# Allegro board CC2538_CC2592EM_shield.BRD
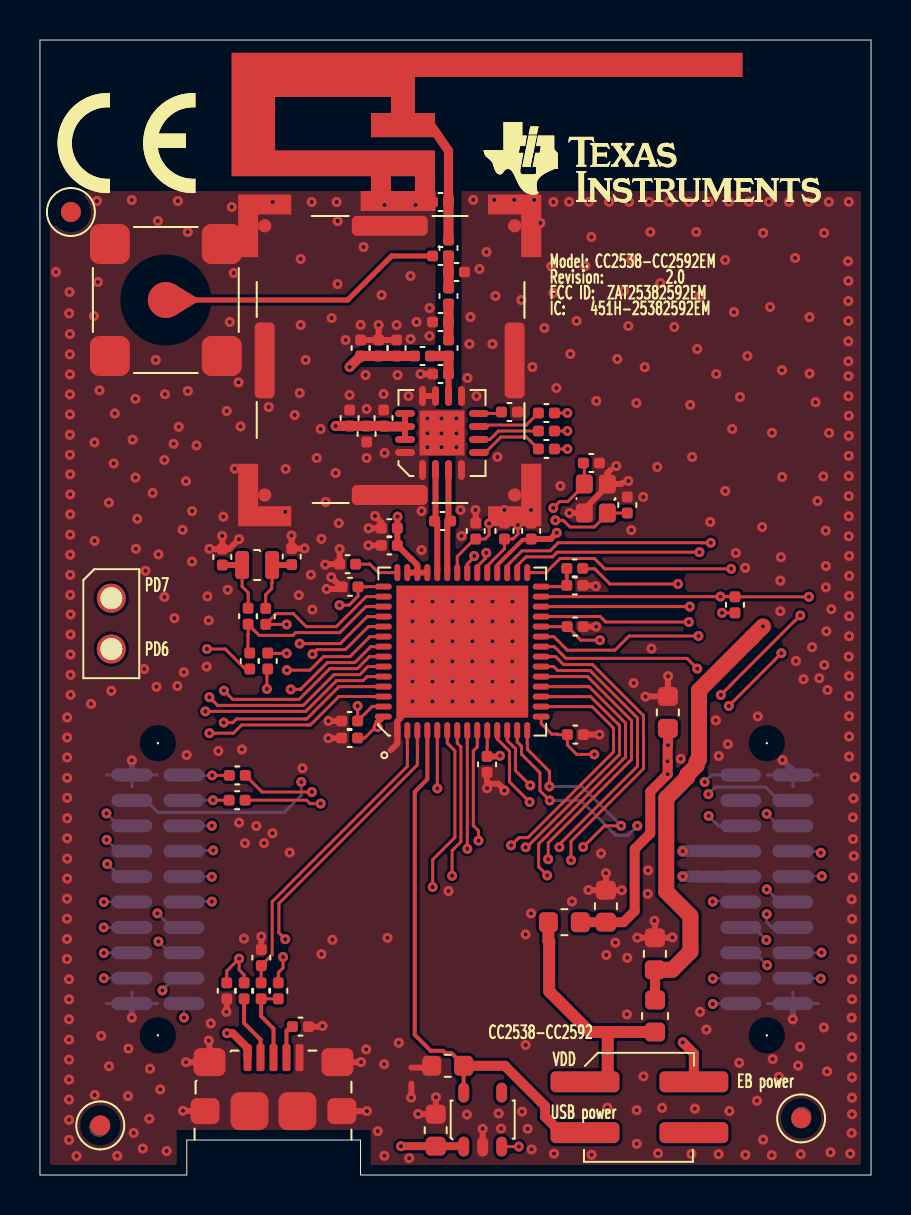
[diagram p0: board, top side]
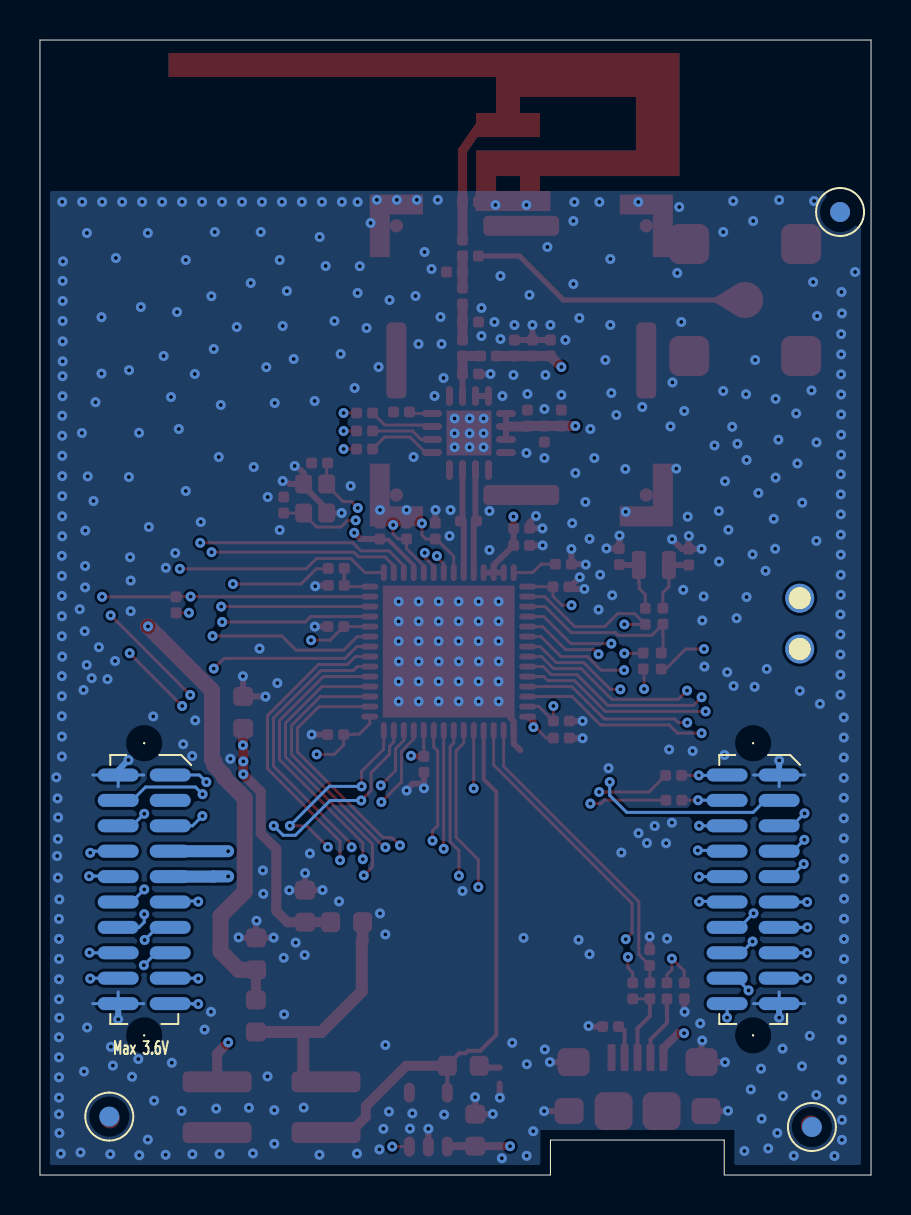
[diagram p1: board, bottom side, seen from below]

Outline 41.6 x 56.75 mm; copper layers: TOP, L2, L3, BOTTOM. Coordinates in mm from the lower left corner of the outline.
Outline path: 0,56.75 0,0 7.35,0 7.35,1.75 16.05,1.75 16.05,0 41.6,0 41.6,56.75 0,56.75

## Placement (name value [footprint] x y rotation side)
A1  DN007  [ANTENNA_DN007]  20.45 48.95 0 top
C2  2.2uF  [CAPC1608X90N]  28.33 12.64 90 top
C3  1uF  [CAPC1608X90N]  19.81 1.44 90 top
C4  DNM  [CAPC1608X90N]  31.43 22.33 90 top
C5  2.2uF  [CAPC1608X90N]  30.78 10.26 90 top
C21  47pF  [CAPC1005X60L]  9.35 9.61 270 top
C31  47pF  [CAPC1005X60L]  11.08 10.47 90 top
C41  1uF  [CAPC1608X90N]  21.21 5.46 180 top
C101  100nF  [CAPC1005X60L]  22.38 20.93 270 top
C151  100nF  [CAPC1005X60L]  26.4 22.02 0 top
C241  100nF  [CAPC1005X60L]  26.39 27.42 0 top
C281  1nF  [CAPC1005X60L]  26.37 29.48 0 top
C321  1uF  [CAPC1005X60L]  24.59 31.8 90 top
C331  100nF  [CAPC1005X60L]  23.25 31.8 90 top
C341  12pF  [CAPC1005X60L]  29.4 33.1 90 top
C351  12pF  [CAPC1005X60L]  27.2 35.6 0 top
C361  100nF  [CAPC1005X60L]  21.81 31.8 90 top
C391  100nF  [CAPC1005X60L]  17.89 32.34 180 top
C392  220pF  [CAPC1005X60L]  17.89 31.48 180 top
C431  100nF  [CAPC1005X60L]  15.92 29.41 180 top
C441  22pF  [CAPC1005X60L]  12.6 30.52 90 top
C451  22pF  [CAPC1005X60L]  9.13 30.5 90 top
C551  1uF  [CAPC1005X60L]  15.9 22.7 180 top
C561  1uF  [CAPC1005X60L]  15.9 21.85 180 top
C3101  3pF  [CAPC1005X60L]  20.45 40.05 180 top
C3103  2.2pF  [CAPC1005X60L]  20.45 42.65 180 top
C3105  0.2pF  [CAPC1005X60L]  20.45 45.15 0 top
C3106  6.8pF  [CAPC1005X60L]  17.85 40.95 90 top
C3107  1nF  [CAPC1005X60L]  16.95 40.95 90 top
C3108  1uF  [CAPC1005X60L]  16.05 40.95 90 top
C3109  DNM  [CAPC1005X60L]  20.45 48.65 180 top
C3110  12pF  [CAPC1005X60L]  20.45 45.95 90 top
C3111  DNM  [CAPC1005X60L]  19.65 45.95 0 top
C3131  12pF  [CAPC1005X60L]  17.2 37.45 90 top
C3132  1nF  [CAPC1005X60L]  16.35 37.45 270 top
C3133  DNM  [CAPC1005X60L]  15.5 37.45 90 top
FIDU1  FIDU_1MM  [FID100X115]  1.55 48.15 0 top
FIDU2  FIDU_1MM  [FID100X115]  3.02 2.48 0 top
FIDU3  FIDU_1MM  [FID100X115]  38.1 2.83 0 top
FIDU4  FIDU_1MM  [FID100X115]  2.96 2.4 180 bottom
FIDU5  FIDU_1MM  [FID100X115]  1.55 48.15 180 bottom
FIDU6  FIDU_1MM  [FID100X115]  38.13 2.92 180 bottom
FL1  BLM18HE152SN1  [FIL_BLM18HE152SN1DN]  27.05 12.64 180 top
FL2  BLM18HE152SN1  [FIL_BLM18HE152SN1DN]  30.79 8.75 270 top
J1  1981568-1  [TYCO_19815681N]  10.39 5.87 270 top
J3  SMA-10V21-TGG  [HUSTSAN_SMA10V21TGGAN]  6.3 43.75 0 top
L3101  4.7nH  [INDC1005X60L]  18.75 40.95 0 top
L3102  1nH  [INDC1005X60L]  20.45 40.95 90 top
L3104  1.8nH  [INDC1005X60L]  20.45 43.55 90 top
L3231  10nH  [INDC1005X60L]  20.55 32.7 180 top
NOREF  -  []  40.6 0 90 top
NOREF#2  -  []  0 53.91 0 top
P1  SFM-110-02-S-D-A-K-TR  [SAMTEC_SFM11002AN]  4.6 20 0 bottom
P2  SFM-110-02-S-D-A-K-TR  [SAMTEC_SFM11002AN]  35.08 20 0 bottom
P5  BB02-HP041-KB3-060B00  [GRADCONN_BB02HP041KB3060B00-4N]  27.28 4.66 270 top
P6  826629-2  [TYCO_826629-2B]  3.57 28.84 270 top
R1  DNM  [RESC1005X40L]  13.44 7.42 180 top
R21  33  [RESC1005X40L]  10.22 9.61 270 top
R31  33  [RESC1005X40L]  11.07 9.61 270 top
R32  1.5k  [RESC1005X40L]  11.93 8.81 90 top
R111  DNM  [RESC1005X40L]  10.27 18.74 180 top
R121  DNM  [RESC1005X40L]  10.28 19.98 180 top
R271  DNM  [RESC1005X40L]  34.79 28.11 90 top
R281  2.2k  [RESC1005X40L]  27.17 30.33 180 top
R421  56k  [RESC1005X40L]  15 30.54 0 top
R441  0  [RESC1005X40L]  11.3 27.53 90 top
R442  DNM  [RESC1005X40L]  11.4 25.3 90 top
R451  0  [RESC1005X40L]  10.42 27.54 90 top
R452  DNM  [RESC1005X40L]  10.5 25.3 90 top
R3051  10k  [RESC1005X40L]  25.75 36.3 180 top
R3061  10k  [RESC1005X40L]  25.75 37.2 180 top
R3071  10k  [RESC1005X40L]  25.75 38.1 180 top
R3081  4.7k  [RESC1005X40L]  23.1 38.15 0 top
SC1  BMIS-201  [MECH_BMIS201]  11.25 34 0 top
U1  CC2538F512RKU  [QFNFC50P800X800X100-57AN]  17.89 22.17 0 top
U2  TLV70233  [SOT95P280X145-5N]  21.21 1.42 0 top
U3  CC2592  [QFNFC65P400X400X100-17AN]  19.15 35.25 0 top
UNK#REFDES  -  []  23.2 52.65 0 top
UNK#REFDES#2  -  []  3.5 49.1 0 top
X1  32MHz  [XTAL_FA128N]  28.4 33.1 90 top
X2  32.768kHz  [XTAL_FC12MN]  11.62 30.5 180 top

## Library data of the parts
A1 = ANTENNA_DN007
C2 C3 C5 C41 = CAPACITOR
C4 = CAPACITOR: alternate symbols: (CAPC1608X90L,CAPC1608X90M)
C21 C31 C101 C151 C241 C281 C321 C331 C341 C351 C361 C391 C392 C431 C441 C451 C551 C561 C3101 C3103 C3105-C3109 C3111 C3131-C3133 = CAPACITOR: alternate symbols: (CAPC1005X60L,CAPC1005X60M)
C3110 = CAPACITOR_HOR: alternate symbols: (CAPC1005X60L,CAPC1005X60M)
FIDU1-FIDU6 = FIDMARK
FL1 = FILTER_2PIN
FL2 = FILTER_2PIN: alternate symbols: (FIL_BLM18HE152SN1DL,FIL_BLM18HE152SN1DM)
J1 = CONN_USB_MICRO_5+6_S
J3 = CONN_COAX_1+4: alternate symbols: (HUSTSAN_SMA10V21TGGL,HUSTSAN_SMA10V21TGGM)
L3101 L3104 L3231 = INDUCTOR: alternate symbols: (INDC1005X60L,INDC1005X60M)
L3102 = INDUCTOR_HOR: alternate symbols: (INDC1005X60L,INDC1005X60M)
P1 P2 = CONN_HEADER_2X10_P_S
P5 = CONN_HEADER_2X2_P_S
P6 = CONN_HEADER_2: alternate symbols: (TYCO_826629-2C,TYCO_826629-2A)
R1 R21 R31 R32 R111 R121 R271 R281 R421 R441 R442 R451 R452 R3051 R3061 R3071 R3081 = RESISTOR: alternate symbols: (RESC1005X40L,RESC1005X40M)
SC1 = SHIELD_COVER_BMIS-201: User Part Number: #PN
U1 = IC_RF_CC2538F512_QFN56_1
U2 = IC_PM_TLV700233_SOT23-5: alternate symbols: (SOT95P280X145-5L,SOT95P280X145-5M)
U3 = IC_RF_CC2592_QFN16_2: alternate symbols: (QFNFC65P400X400X100-17AL,QFNFC65P400X400X100-17AM)
X1 = XTAL_4
X2 = XTAL: alternate symbols: (XTAL_FC12ML,XTAL_FC12MM)

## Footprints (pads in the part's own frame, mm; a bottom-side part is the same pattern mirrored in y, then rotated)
ANTENNA_DN007
  rect 0.46x0.5 smd: 1(0,0)
  rect 1x0.5 smd: 2(-1.18,0) 3(-3.38,0)
CAPC1005X60L
  custom 0.135x0.135 smd: 1(0,0) 2(0.8,0)
CAPC1608X90N
  custom 0.237x0.237 smd: 1(0,0) 2(1.6,0)
FID100X115
  oval 1x1 smd: 1(0,0)
FIL_BLM18HE152SN1DN
  custom 0.237x0.237 smd: 1(0,0) 2(1.6,0)
GRADCONN_BB02HP041KB3060B00-4N
  custom 0.263x0.263 smd: 1(0,0) 2(0,5.45) 3(2.54,0) 4(2.54,5.45)
HUSTSAN_SMA10V21TGGAN
  round 1.801 smd: 1(0,0)
  custom 0.5x0.5 smd: 2(-2.8,-2.8) 3(2.8,-2.8) 4(2.8,2.8) 5(-2.8,2.8)
INDC1005X60L
  custom 0.135x0.135 smd: 1(0,0) 2(0.8,0)
MECH_BMIS201
  custom 0.665x0.665 smd: 1(0,0) 3(12.51,0) 5(12.51,13.46) 7(0,13.46)
  custom 0.25x0.25 smd: 2(6.26,0) 4(12.51,6.73) 6(6.26,13.46) 8(0,6.73)
QFNFC50P800X800X100-57AN
  oval 0.3x0.851 smd: 1(0,0.051) 2(0.5,0.051) 3(1.001,0.051) 4(1.501,0.051) 5(1.999,0.051) 6(2.499,0.051) 7(3,0.051) 8(3.5,0.051) 9(4,0.051) 10(4.501,0.051) 11(5.001,0.051) 12(5.499,0.051) 13(6,0.051) 14(6.5,0.051) 29(6.5,7.95) 30(6,7.95) 31(5.499,7.95) 32(5.001,7.95) 33(4.501,7.95) 34(4,7.95) 35(3.5,7.95) 36(3,7.95) 37(2.499,7.95) 38(1.999,7.95) 39(1.501,7.95) 40(1.001,7.95) 41(0.5,7.95) 42(0,7.95)
  oval 0.851x0.3 smd: 15(7.201,0.749) 16(7.201,1.25) 17(7.201,1.75) 18(7.201,2.25) 19(7.201,2.751) 20(7.201,3.251) 21(7.201,3.749) 22(7.201,4.249) 23(7.201,4.75) 24(7.201,5.25) 25(7.201,5.751) 26(7.201,6.251) 27(7.201,6.749) 28(7.201,7.249) 43(-0.701,7.249) 44(-0.701,6.749) 45(-0.701,6.251) 46(-0.701,5.751) 47(-0.701,5.25) 48(-0.701,4.75) 49(-0.701,4.249) 50(-0.701,3.749) 51(-0.701,3.251) 52(-0.701,2.751) 53(-0.701,2.25) 54(-0.701,1.75) 55(-0.701,1.25) 56(-0.701,0.749)
  rect 6.599x6.599 smd: 57(3.251,4)
QFNFC65P400X400X100-17AN
  oval 0.35x1 smd: 1(0,0) 2(0.65,0) 3(1.3,0) 4(1.95,0) 9(1.95,3.7) 10(1.3,3.7) 11(0.65,3.7) 12(0,3.7)
  oval 1x0.35 smd: 5(2.825,0.875) 6(2.825,1.525) 7(2.825,2.175) 8(2.825,2.825) 13(-0.875,2.825) 14(-0.875,2.175) 15(-0.875,1.525) 16(-0.875,0.875)
  rect 2.25x2.25 smd: 17(0.975,1.85)
RESC1005X40L
  custom 0.135x0.135 smd: 1(0,0) 2(0.8,0)
SAMTEC_SFM11002AN
  round 0.099 hole 1.501 unplated: (1.302,-1.588) (1.302,13.018)
  oval 2.05x0.65 smd: 1(0,0) 2(2.604,0) 3(0,1.27) 4(2.604,1.27) 5(0,2.54) 6(2.604,2.54) 7(0,3.81) 8(2.604,3.81) 9(0,5.08) 10(2.604,5.08) 11(0,6.35) 12(2.604,6.35) 13(0,7.62) 14(2.604,7.62) 15(0,8.89) 16(2.604,8.89) 17(0,10.16) 18(2.604,10.16) 19(0,11.43) 20(2.604,11.43)
SOT95P280X145-5N
  oval 0.549x1.001 smd: 1(0,0) 2(0.95,0) 3(1.9,0) 4(1.9,2.7) 5(0,2.7)
TYCO_826629-2B
  round 1.45 hole 1.1: 1(0,0) 2(2.54,0)
TYCO_19815681N
  custom 0.1x0.1 smd: 1(0,0) 2(0,0.65) 3(0,1.3) 4(0,1.95) 5(0,2.6)
  custom 0.35x0.35 smd: 6(0.225,-1.903) 7(0.225,4.497)
  custom 0.325x0.325 smd: 8(2.675,-2.128) 9(2.675,4.722)
  custom 0.475x0.475 smd: 10(2.675,0.097) 11(2.675,2.497)
XTAL_FA128N
  custom 0.212x0.212 smd: 1(0,0) 2(1.45,0) 3(1.45,1.151) 4(0,1.151)
XTAL_FC12MN
  custom 0.175x0.175 smd: 1(0,0) 2(1.5,0)

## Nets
DVDD_USB: C41.1 P5.3 U1.4(DVDD_USB) U2.5(OUT)
GND: A1.2(GND_2) A1.3(GND_3) C2.2 C3.2 C4.2 C5.2 C21.2 C31.2 C41.2 C101.2 C151.2 C241.2 C281.2 C321.2 C331.2 C341.2 C351.2 C361.2 C391.2 C392.2 C431.2 C441.2 C451.2 C551.2 C561.2 C3101.2 C3103.2 C3105.2 C3106.2 C3107.2 C3108.2 C3109.2 C3131.2 C3132.2 C3133.2 J1.5(GND#5) J1.6(GND#6) J1.7(GND#7) J1.8(GND#8) J1.9(GND#9) J1.10(GND#10) J1.11(GND#11) J3.2 J3.3 J3.4 J3.5 P1.1 P1.19 P2.2 P2.20 R1.1 R421.1 R3081.2 SC1.1(GND#1) SC1.2(GND#2) SC1.3(GND#3) SC1.4(GND#4) SC1.5(GND#5) SC1.6(GND#6) SC1.7(GND#7) SC1.8(GND#8) U1.1(DGND_USB) U1.57(AGND) U2.2(GND) U3.1(GND#1) U3.4(GND#4) U3.9(GND#9) U3.11(GND#11) U3.12(GND#12) U3.16(GND#16) U3.17(EGP/GND) X1.2 X1.4
VDD_CC2538: C2.1 C4.1 C101.1 C151.1 C241.1 C331.1 C361.1 C391.1 C392.1 C431.1 C551.1 FL1.1 U1.10(VDD#10) U1.15(VDD#15) U1.24(VDD#24) U1.33(AVDD#33) U1.36(AVDD#36) U1.39(AVDD#39) U1.40(AVDD#40) U1.41(AVDD#41) U1.43(AVDD_GUARD) U1.55(AVDD_DREG/DVDD1)
VDD_CC2592: C5.1 C3106.1 C3107.1 C3108.1 C3131.1 C3132.1 C3133.1 FL2.1 L3101.1 U3.13(VDD_LNA) U3.14(VDD_BIAS) U3.15(VDD_PA)
VDD_EB: P2.7 P2.9 P5.2
JTAG_TCK: P2.1 U1.47(JTAG_TCK)
JTAG_TMS: P2.4 U1.46(JTAG_TMS)
NRESET: P2.15 R281.1
PA0: P1.7 U1.16(PA0)
PA1: P1.9 U1.17(PA1)
PA2: P1.16 U1.18(PA2)
PA3: P1.14 U1.19(PA3)
PA4: P1.18 U1.20(PA4)
PA5: P1.20 U1.21(PA5)
PA6: P2.5 U1.22(PA6)
PA7: P2.6 U1.23(PA7)
PB0: P1.3 U1.5(PB0)
PB1: P1.5 U1.54(PB1)
PB2: P1.11 U1.53(PB2)
PB3: P1.13 U1.52(PB3)
PB4: P1.15 U1.51(PB4)
PB5: P1.17 U1.50(PB5)
PB6/JTAG_TDI: P2.17 U1.49(PB6)
PB7/JTAG_TDO: P2.19 U1.48(PB7)
PC0: P2.11 R32.2 U1.14(PC0)
PC1: P2.13 U1.13(PC1)
PC2: R121.1 R3061.1 U1.12(PC2)
PC3: R111.1 R3051.1 U1.11(PC3)
PC4: P1.6 U1.9(PC4)
PC5: P1.8 U1.8(PC5)
PC6: P1.10 U1.7(PC6)
PC7: P1.12 U1.6(PC7)
PD0: P2.12 U1.25(PD0)
PD1: P2.14 U1.26(PD1)
PD2: R271.2 R3071.1 U1.27(PD2)
PD3: P2.18 U1.29(PD3)
PD4: P2.8 U1.30(PD4)
PD5: P2.10 U1.31(PD5)
PD6: P6.1 R442.1
PD7: P6.2 R452.1
USB_N: C21.1 R21.1 U1.3(USB_N)
USB_P: C31.1 R31.1 U1.2(USB_P)
N05346: R421.2 U1.42(R_BIAS)
N19179: J1.3(D+) R31.2 R32.1
N23099: C341.1 U1.34(XOSC32M_Q1) X1.1
N24069: J1.4(ID) R1.2
N28244: J1.2(D-) R21.2
N31525: C351.1 U1.35(XOSC32M_Q2) X1.3
N50825: C3.1 J1.1(VBUS) U2.1(IN) U2.3(EN)
N61958: P2.16 R271.1
N118182: FL1.2 FL2.2 P5.1
N130966: R3081.1 U3.8(BIAS)
N292030: P1.2 R121.2
N292096: P1.4 R111.2
N302598: A1.1(FEED_1) C3109.1 C3110.2
N313805: L3231.1 U1.37(RF_P) U3.3(RF_P)
N313817: L3231.2 U1.38(RF_N) U3.2(RF_N)
N314459: R3071.2 U3.7(HGM)
N314634: R3061.2 U3.6(LNA_EN)
N315094: R3051.2 U3.5(PA_EN)
N333392: C3101.1 L3101.2 L3102.1 U3.10(ANT)
N333448: C3105.1 C3110.1 C3111.2 L3104.2
N333456: C3103.1 L3102.2 L3104.1
N355972: C3111.1 J3.1
N359155: C441.1 R441.2 X2.1
N359159: C451.1 R451.2 X2.2
N359209: R451.1 R452.2 U1.45(PD7/XOSC32K_Q2)
N359245: R441.1 R442.2 U1.44(PD6/XOSC32K_Q1)
N359999: C281.1 R281.2 U1.28(NRESET)
N362623: C321.1 C561.1 U1.32(DVDD_REG) U1.56(DCOUPL)

Pads without a net: FIDU1 1; FIDU2 1; FIDU3 1; FIDU4 1; FIDU5 1; FIDU6 1; P2 3; P5 4; U2 4

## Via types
v1: diameter 0.5, hole 0.2, TOP to BOTTOM, 581 vias

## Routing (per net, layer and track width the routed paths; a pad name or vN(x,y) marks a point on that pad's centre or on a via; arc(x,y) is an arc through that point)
DVDD_USB: length 27.7
  TOP w0.2: U2.5 C41.1 21.21,5.48 20.61,6.09 20.29,6.09 20.17,6.21 19.56,6.21 18.76,7.01 18.76,19.16 19.39,19.79 U1.4 ; P5.3 27.27,2.11
  TOP w0.5: C41.1 23.27,5.46 25.29,3.44 25.29,2.91 26.08,2.12 P5.3
GND: length 61.1
  TOP w0.15: C561.2 15.09,21.84 ; C551.2 15.1,22.6 ; 19.52,5.37 C41.2
  TOP w0.3: X1.2 29.1,34.55 29.15,34.6 ; X1.2 28.4,34.45 27.25,33.3 X1.4 v1(26.5,33.1) ; X1.2 28.4,35.1 28.55,35.25 ; 18.59,5.37 19.52,5.37 ; C5.2 31.49,11.86 31.51,11.88 v1(31.66,11.88) ; C5.2 30.07,11.86 30.06,11.87 v1(29.9,11.87) ; C5.2 30.79,11.87 30.79,12.61 30.76,12.64 v1(30.76,12.71) ; 15.06,29.41 15.03,29.41 14.92,29.3 v1(14.35,29.3) ; 15.06,29.41 v1(14.58,29.89) ; 15.06,29.41 C431.2 ; v1(9.96,31.79) 9.47,31.3 C451.2 ; C31.2 v1(11.08,11.92) ; C241.2 v1(27.84,27.42) ; v1(14.14,7.45) 14.03,7.45 14,7.42 R1.1 ; v1(16.45,32.33) 16.61,32.33 16.62,32.34 C391.2 17.1,32.34 17.1,32.62 v1(16.77,32.95) ; v1(23.25,19.22) 23.25,19.26 22.95,19.56 22.38,19.56 ; v1(18.93,3.05) 19.04,3.05 19.05,3.04 C3.2 19.81,3.8 19.82,3.81 v1(19.82,3.89) ; 14.89,5.64 v1(16.07,5.64) ; 22.38,19.56 v1(22.38,19.34) ; 22.38,19.56 C101.2 ; C392.2 v1(16.44,31.48) ; v1(29.12,14.24) 29.12,14.24 C2.2 ; v1(12.59,31.97) 12.59,31.73 12.6,31.72 C441.2 13.16,31.32 13.17,31.33 v1(13.25,31.33) ; J1.8 7.39,3.19 7.38,3.21 v1(7.16,3.21) ; v1(30.31,23.92) 30.32,23.93 C4.2 31.43,24.93 v1(31.44,24.94) ; v1(8.48,31.31) 8.59,31.31 8.6,31.3 C451.2 ; v1(27.45,14.25) 27.65,14.25 27.66,14.24 C2.2 ; v1(9.12,31.95) 9.12,31.82 9.13,31.81 C451.2 ; 15.09,21.84 v1(14.44,21.84) ; v1(28,22.02) C151.2 ; C551.2 v1(14.44,22.7) ; C3101.2 v1(19.05,40.05) ; v1(14.28,30.52) 14.3,30.54 R421.1 v1(15,31.3) ; C2.2 v1(28.33,15.09) ; J1.9 v1(16.36,3.19) ; C21.2 9.35,8.19 9.33,8.17 v1(9.33,8.16) ; v1(23.08,2.32) 23.09,2.31 ; 17.56,21.24 17.89,21.57 U1.1 17.89,22.69 18.05,22.85 18.05,23.05 ; C321.2 24.58,32.61 v1(24.58,33.25) ; C3107.2 C3108.2 ; C3107.2 16.95,42.3 ; C3107.2 C3106.2 ; v1(27.82,29.44) 27.8,29.44 27.76,29.48 C281.2 ; v1(18.58,3.87) 18.58,4.06 18.59,4.07 18.59,4.57 ; v1(22.16,2.31) U2.2 ; v1(8.45,6.72) 8.45,6.6 8.49,6.56 8.49,5.64 7.55,5.64 7.55,5.64 v1(7.31,5.64) ; v1(23.25,33.25) C331.2 ; v1(21.8,33.25) 21.8,33.2 21.81,33.19 C361.2 ; U3.11 U3.12
  BOTTOM w0.15: 3.32,8.57 P1.19 ; P1.19 5.88,8.57 ; P1.19 4.6,9.15 ; P2.2 38.96,20 ; P2.2 37.68,19.42 ; P2.2 36.41,20 ; P2.20 38.96,8.57 ; P2.20 36.41,8.57 ; P2.20 37.68,9.15 ; 3.32,20 P1.1 ; P1.1 4.6,19.42 ; P1.1 5.88,20
  BOTTOM w0.3: v1(37.17,20.75) 37.68,20.24 P2.2 ; P1.19 v1(4.6,7.87) ; P2.20 v1(37.68,7.78) ; P1.1 v1(4.6,20.73)
  vias: v1(0.8,45.15) v1(1.37,22.88) v1(1.36,21.88) v1(1.36,20.88) v1(1.36,19.86) v1(1.36,18.86) v1(1.36,17.83) v1(1.36,16.83) v1(1.36,15.82) v1(1.36,14.82) v1(1.35,13.81) v1(1.35,12.81) v1(1.35,11.8) v1(1.35,10.8) v1(1.48,44.15) v1(1.46,43.08) v1(1.5,42.05) v1(1.5,41.03) v1(1.5,40.03) v1(1.5,39.03) v1(1.5,38.03) v1(1.5,37.01) v1(1.5,36.01) v1(1.52,35.03) v1(1.52,34.03) v1(1.52,33.03) v1(1.52,32.02) v1(1.52,31.02) v1(1.52,30) v1(1.52,29) v1(1.53,28.03) v1(1.53,27.02) v1(1.53,26.02) v1(1.53,25.01) v1(1.53,24.01) v1(1.46,9.79) v1(1.45,8.78) v1(1.45,7.78) v1(1.45,6.77) v1(1.45,5.77) v1(1.46,4.77) v1(1.46,3.77) v1(1.46,2.76) v1(1.46,1.76) v1(1.83,0.95) v1(2.56,23.56) v1(2.7,42.95) v1(2.73,36.63) v1(2.74,31.71) v1(2.74,4) v1(2.85,48.7) v1(2.9,44.65) v1(2.98,39.23) v1(3.07,6.96) v1(3.45,33.62) v1(3.46,5.44) v1(3.57,24.21) v1(3.75,38.08) v1(3.69,35.58) v1(3.87,0.96) v1(4.43,6.32) v1(4.41,3.95) v1(4.6,48.75) v1(4.64,36.77) v1(4.69,2.1) v1(4.78,38.81) v1(4.78,34.87) v1(4.8,31.31) v1(4.87,32.81) v1(5.15,1.33) v1(5.22,25.3) v1(5.28,30.21) v1(5.51,5.32) v1(5.48,2.82) v1(5.64,34.1) v1(5.8,40.75) v1(5.83,24.41) v1(5.9,47.7) v1(5.93,31.03) v1(6.02,4.28) v1(6.23,35.75) v1(6.23,28.9) v1(6.26,39.04) v1(6.34,1.2) v1(6.69,36.56) v1(6.73,27.84) v1(6.9,48.7) v1(6.95,37.41) v1(6.88,24.45) v1(7.14,32.26) v1(7.2,25.14) v1(7.31,34.69) v1(7.34,21) v1(7.4,47.15) v1(7.4,39.2) v1(7.62,33.2) v1(7.61,30.67) v1(7.84,36.48) v1(8.34,25.42) v1(8.38,28.93) v1(8.45,27.73) v1(8.55,7.58) v1(8.93,21.2) v1(9.18,32.92) v1(9.35,38.2) v1(9.4,29.26) v1(9.5,42.65) v1(9.6,48.4) v1(9.7,45.1) v1(9.75,35.32) v1(9.94,39.63) v1(10.04,37.43) v1(9.97,17.62) v1(10.11,21.28) v1(10.21,11.82) v1(10.26,16.59) v1(10.83,17.45) v1(11.22,16.6) v1(11.45,38.4) v1(11.65,48.65) v1(11.64,17.09) v1(12.3,35.3) v1(12.28,33.16) v1(12.5,16.12) v1(12.75,38) v1(13,39.1) v1(12.96,28.99) v1(13.05,45.8) v1(13.05,42.5) v1(13.14,20.34) v1(13.3,40.75) v1(13.6,48.65) v1(13.56,30.01) v1(13.64,28.27) v1(13.85,35.85) v1(14.05,37.3) v1(14.09,31.81) v1(14.09,11.04) v1(14.3,33.65) v1(14.6,42.85) v1(14.64,11.76) v1(14.85,48.65) v1(14.8,35.1) v1(14.9,47.7) v1(14.9,44.55) v1(14.96,32.59) v1(15.3,41.75) v1(15.5,39) v1(16.05,42.5) v1(16.2,46.4) v1(16.3,40) v1(16.33,6.28) v1(16.35,38.3) v1(16.35,35.85) v1(16.95,42.5) v1(16.91,2.19) v1(17.1,44) v1(17.2,39.05) v1(17.23,5.54) v1(17.24,0.96) v1(17.25,48.5) v1(17.25,36.1) v1(17.39,11.86) v1(17.85,42.5) v1(17.9,40) v1(17.96,6.61) v1(18.45,38.95) v1(18.48,0.84) v1(18.55,44.95) v1(18.55,41.8) v1(18.64,28.67) v1(18.64,27.68) v1(18.65,26.69) v1(18.64,25.68) v1(18.65,24.67) v1(18.64,23.68) v1(18.8,48.5) v1(18.85,42.65) v1(19.1,33.2) v1(19.1,31.25) v1(19.39,37.83) v1(19.39,37.08) v1(19.4,36.39) v1(19.5,43.35) v1(19.5,41.95) v1(19.64,28.67) v1(19.64,27.68) v1(19.65,26.69) v1(19.64,25.68) v1(19.65,24.67) v1(19.64,23.68) v1(20.09,37.83) v1(20.09,37.08) v1(20.1,36.39) v1(20.45,14.2) v1(20.64,28.67) v1(20.64,27.68) v1(20.65,26.69) v1(20.64,25.68) v1(20.65,24.67) v1(20.64,23.68) v1(20.84,37.83) v1(20.84,37.08) v1(20.85,36.39) v1(21.05,33.25) v1(21.1,31.95) v1(21.4,39.85) v1(21.37,3.02) v1(21.5,41.55) v1(21.55,42.9) v1(21.64,28.67) v1(21.64,27.68) v1(21.65,26.69) v1(21.64,25.68) v1(21.65,24.67) v1(21.64,23.68) v1(21.69,48.76) v1(21.85,38.95) v1(22,45.3) v1(22.35,46.15) v1(22.65,28.67) v1(22.65,27.68) v1(22.65,26.69) v1(22.64,25.68) v1(22.65,24.67) v1(22.64,23.68) v1(22.74,48.76) v1(22.65,41.55) v1(22.8,43.95) v1(22.9,35.9) v1(22.96,3.08) v1(23.65,28.67) v1(23.65,27.68) v1(23.65,26.69) v1(23.64,25.68) v1(23.65,24.67) v1(23.64,23.68) v1(23.74,48.76) v1(24.1,43.75) v1(24.13,3.17) v1(24.31,12.03) v1(24.31,6.5) v1(24.41,2.31) v1(24.58,13.08) v1(24.61,1.28) v1(24.74,48.76) v1(24.65,40.4) v1(25.05,47.6) v1(25.25,42.35) v1(25.59,45.44) v1(25.7,48.65) v1(25.7,44.1) v1(25.73,1.07) v1(25.85,39.35) v1(26.05,34.45) v1(26.49,48.66) v1(26.55,41.05) v1(26.63,13.68) v1(26.86,42.7) v1(27.3,45.45) v1(27.49,48.66) v1(27.6,46.9) v1(27.61,1.01) v1(27.85,38.7) v1(28.09,16.08) v1(28.35,11) v1(28.4,3.37) v1(28.49,48.66) v1(28.85,35.45) v1(28.8,11.62) v1(28.9,40.8) v1(29.24,44.2) v1(29.45,42.45) v1(29.45,34.7) v1(29.4,10.86) v1(29.38,8.03) v1(29.49,48.66) v1(29.6,45.75) v1(29.6,32.25) v1(29.72,24.6) v1(29.85,38.6) v1(29.87,3.24) v1(29.87,1.56) v1(30.2,33.9) v1(30.21,4.93) v1(30.27,40.39) v1(30.44,15.23) v1(30.42,14.06) v1(30.49,48.66) v1(30.55,47.15) v1(30.61,26.32) v1(30.9,35.4) v1(30.94,1.08) v1(31.05,44.6) v1(31.14,3.36) v1(31.49,48.66) v1(31.75,42.4) v1(32.07,20.81) v1(32.49,48.66) v1(32.55,38.5) v1(32.61,1.05) v1(32.65,35.9) v1(32.85,47.15) v1(32.78,3.32) v1(32.9,41.3) v1(33.02,43.94) v1(33.04,8.16) v1(33.36,7.27) v1(33.49,48.66) v1(33.55,32.65) v1(33.85,40.05) v1(33.83,22.73) v1(33.98,20.95) v1(33.97,1.04) v1(34.3,45.75) v1(34.3,34.2) v1(34.43,21.54) v1(34.49,48.66) v1(34.51,3.2) v1(34.74,43.15) v1(34.65,37.3) v1(34.83,31.1) v1(35.04,38.9) v1(35,5.61) v1(35.3,30.36) v1(35.31,1.01) v1(35.41,40.95) v1(35.49,48.66) v1(35.93,22.93) v1(35.89,3.72) v1(36.2,47.1) v1(36.15,32.4) v1(36.2,1.77) v1(36.49,48.66) v1(36.55,43.4) v1(36.64,37.11) v1(36.63,0.99) v1(36.68,5.8) v1(36.99,4.91) v1(37.14,40.24) v1(37.09,30.89) v1(37.06,29.72) v1(37.06,28.19) v1(37.15,34.9) v1(37.49,48.66) v1(37.8,45.85) v1(37.84,25.7) v1(37.95,5.47) v1(38.05,6.41) v1(38.08,1.04) v1(38.22,24.79) v1(38.49,48.66) v1(38.52,42.89) v1(38.52,40.07) v1(38.65,26.39) v1(38.82,38.64) v1(38.92,33.7) v1(39.01,24.84) v1(39.21,34.93) v1(39.24,7.38) v1(39.25,47.1) v1(39.33,32.22) v1(39.34,30.45) v1(39.34,29.38) v1(39.26,25.5) v1(39.36,27.19) v1(39.42,24.25) v1(39.4,5.18) v1(39.49,48.66) v1(39.5,37.1) v1(39.61,28.29) v1(39.57,1.13) v1(40.45,45.68) v1(40.49,48.66) v1(40.46,44.7) v1(40.46,43.7) v1(40.46,42.7) v1(40.46,41.69) v1(40.46,40.69) v1(40.47,39.94) v1(40.47,38.94) v1(40.49,37.96) v1(40.49,36.96) v1(40.49,35.96) v1(40.49,34.94) v1(40.49,33.94) v1(40.49,32.94) v1(40.49,31.94) v1(40.5,30.96) v1(40.5,29.95) v1(40.5,28.95) v1(40.5,27.94) v1(40.5,26.94) v1(40.49,25.92) v1(40.5,24.94) v1(40.5,23.94) v1(40.5,22.94) v1(40.5,21.92) v1(40.5,20.92) v1(40.63,13.78) v1(40.65,12.81) v1(40.65,11.8) v1(40.65,10.8) v1(40.65,9.79) v1(40.65,8.79) v1(40.63,7.86) v1(40.65,6.89) v1(40.65,5.88) v1(40.65,4.88) v1(40.65,3.87) v1(40.65,3.04) v1(40.63,2.1) v1(40.56,1.07) v1(40.72,18.83) v1(40.69,17.88) v1(40.7,16.8) v1(40.74,15.95) v1(40.7,14.87) v1(40.78,19.88)
VDD_CC2538: length 38.1
  TOP w0.15: v1(27.75,21.03) 26.87,21.03 26.4,21.5 C151.1 25.91,22.02 25.89,22.05 25.61,22.05 25.09,22.57 U1.15 ; v1(23.92,32.5) 23.93,32.49 23.93,32.06 23.67,31.8 C331.1 23.25,31.31 22.39,30.45 U1.33 ; v1(22.48,32.58) 22.48,32 22.28,31.8 C361.1 21.8,31.79 21.74,31.79 20.89,30.93 U1.36 ; U1.55 17.18,23.43 16.63,23.43 C551.1 15.89,22.7 15.9,22.71 v1(15.9,23.45) ; C391.1 17.89,32.33 ; U1.24 C241.1 26.39,27.42 27.07,26.74 v1(28.03,26.74) ; C101.1 22.38,21.41 22.39,21.42 U1.10 ; v1(14.99,28.49) 15.47,28.49 15.92,28.94 C431.1 16.4,29.41 16.41,29.42 U1.43 ; 23,20.93 v1(23.03,20.96)
  TOP w0.3: C101.1 23,20.93 ; v1(17.9,32.92) 17.9,32.34 17.89,32.33 C392.1 17.89,31.48 18.55,30.82 18.57,30.82 18.82,30.57 18.82,30.56 18.89,30.48 U1.40 ; U1.40 U1.39 ; U1.40 U1.41
  TOP w0.5: C4.1 31.44,22.32 v1(31.44,21.49) 31.42,21.47 v1(31.42,20.68) v1(31.42,20.04) 30.55,19.17 30.55,17.08 29.77,16.3 29.77,13.2 29.21,12.64 C2.1 FL1.1
  L3 w0.15: 23.02,20.95 v1(23.03,20.96)
VDD_CC2592: length 63.2
  TOP w0.15: 30.79,10.26 C5.1
  TOP w0.3: U3.13 U3.14 U3.15
  TOP w0.5: L3101.1 C3106.1 C3107.1 C3108.1 v1(15.5,40.4) ; 30.79,8.74 FL2.1 30.79,10.26 ; v1(14.8,37.45) C3133.1 C3132.1 C3131.1 17.22,37.42 U3.14
  TOP w0.8: v1(36.19,27.43) 35.64,26.88 35.64,26.88 32.99,24.23 32.99,20.79 32.87,20.67 32.87,20.48 32.4,20.01 32.4,19.89 31.35,18.84 31.35,14.16 32.56,12.95 32.56,11.17 31.65,10.26 30.79,10.26
  L3 w0.5: v1(15.5,40.4) 14.8,39.7 v1(14.8,37.45) 14.8,36.2 15.85,35.15 26.95,35.15 27.9,36.1 31.3,36.1 36.19,31.21
  L3 w0.8: v1(36.19,27.43) 36.19,31.21
VDD_EB: length 17.7
  TOP w0.5: v1(32.18,6.63) 32.73,6.08 P5.2
  L3 w0.5: v1(32.18,6.63) 32.18,11.48 32.31,11.61 32.31,12.15 32.18,12.28 v1(32.18,14.93) v1(32.18,16.19)
  BOTTOM w0.6: P2.9 32.92,14.92 32.91,14.93 v1(32.18,14.93) ; P2.7 v1(32.18,16.19)
JTAG_TCK: length 35.1
  TOP w0.15: v1(13.64,26.04) 13.87,26.27 15.29,26.27 16.44,27.42 U1.47
  L3 w0.15: v1(33.27,19.65) 31.91,18.29 28.75,18.29 28.55,18.09 13.8,18.09 12.56,19.33 12.56,23.08 12.97,23.49 13.03,23.54 13.16,23.67 13.16,23.67 13.64,24.15 v1(13.64,26.04)
  BOTTOM w0.15: v1(33.27,19.65) 33.62,20 P2.1
JTAG_TMS: length 39.4
  TOP w0.15: U1.46 16.38,27.92 15.03,26.57 v1(13,26.57)
  L3 w0.15: v1(13,26.57) 13,26.06 13.09,25.97 13.09,24.03 12.86,23.8 12.81,23.75 12.26,23.2 12.26,19.21 13.68,17.79 28.67,17.79 28.87,17.99 32.41,17.99 v1(33.46,19.04)
  BOTTOM w0.15: P2.4 36.98,18.73 36.31,19.4 33.82,19.4 v1(33.46,19.04)
NRESET: length 28.8
  TOP w0.15: R281.1 27.19,30.31 27.77,30.31 28.53,29.55 v1(31.94,29.55)
  L3 w0.15: v1(31.94,29.55) 31.94,29.1 31.93,29.09 31.93,26.88 32.19,26.63 32.88,25.93 33.41,25.93 33.41,25.93 33.43,25.91 34.36,24.97 35.3,24.04 35.3,13.13 36.15,12.28 36.77,12.28 37.04,12.01 37.04,11.13 v1(36.4,10.49)
  BOTTOM w0.15: P2.15 35.23,10.96 35.93,10.96 v1(36.4,10.49)
PA0: length 35.5
  TOP w0.15: U1.16 27.64,23.42 28.71,22.35 28.71,21.15 24.43,16.87 24,16.87 23.98,16.85 23.93,16.83 v1(23.58,16.48)
  L3 w0.15: v1(23.58,16.48) 22.91,15.81 19.43,15.81 18.5,14.88 9.94,14.88 9.14,15.69 8.47,15.69 7.72,16.43 3.67,16.43 v1(3.34,16.76)
  BOTTOM w0.15: v1(3.34,16.76) 3.76,16.34 4.45,16.34 P1.7
PA1: length 36.6
  TOP w0.15: v1(24.31,16.39) 24.32,16.39 24.37,16.39 29.01,21.03 29.01,22.47 27.56,23.92 U1.17
  L3 w0.15: v1(24.31,16.39) 23.44,15.51 19.55,15.51 18.62,14.58 9.82,14.58 9.01,15.39 8.34,15.39 7.6,16.13 3.95,16.13 v1(3.37,15.55)
  BOTTOM w0.15: v1(3.37,15.55) 4,14.92 P1.9
PA2: length 36.9
  TOP w0.15: v1(25.39,14.98) 24.96,15.41 24.96,16.55 29.31,20.9 29.31,22.6 27.49,24.42 U1.18
  L3 w0.15: v1(25.39,14.98) 23.95,14.98 22.35,13.38 9.76,13.38 8.05,11.67 v1(5.93,11.67)
  BOTTOM w0.15: v1(5.93,11.67) 6.49,11.11 P1.16
PA3: length 36.4
  TOP w0.15: U1.19 27.41,24.92 29.61,22.72 29.61,20.78 25.44,16.61 v1(25.44,15.79)
  L3 w0.15: v1(5.88,13.08) 9.02,13.08 9.62,13.68 22.1,13.68 24.21,15.79 v1(25.44,15.79)
  BOTTOM w0.15: v1(5.88,13.08) 6.4,12.56 6.4,12.53 6.55,12.38 P1.14
PA4: length 39
  TOP w0.15: v1(26,16.39) 26,16.53 29.91,20.44 29.91,22.85 27.54,25.22 25.92,25.22 25.72,25.42 U1.20
  L3 w0.15: v1(6.13,9.23) 9.97,13.07 10.06,13.07 10.07,13.08 22.55,13.08 23.92,14.45 25.55,14.45 26,14.9 v1(26,16.39)
  BOTTOM w0.15: v1(6.13,9.23) 6.74,9.84 P1.18
PA5: length 40.4
  TOP w0.15: v1(26.58,15.74) 26.58,16.69 30.21,20.32 30.21,22.97 27.66,25.52 26.21,25.52 25.81,25.92 U1.21
  L3 w0.15: v1(26.58,15.74) 26.58,14.99 25.74,14.15 24.06,14.15 22.69,12.78 10.19,12.78 8.21,10.8 8.21,8.23 7.85,7.87 v1(7.21,7.87)
  BOTTOM w0.15: v1(7.21,7.87) 7.21,8.08 7.2,8.09 P1.20
PA6: length 19.4
  TOP w0.15: U1.22 25.74,26.42 26.33,25.83 32.39,25.83 v1(32.9,25.32)
  L3 w0.15: v1(32.9,25.32) 33.59,25.32 34.24,24.67 35,23.91 35,19.48 v1(33.47,17.95)
  BOTTOM w0.15: v1(33.47,17.95) 33.96,17.46 P2.5
PA7: length 22.1
  TOP w0.15: v1(32.96,26.95) 29.49,26.95 28.78,26.24 26.4,26.24 25.72,26.92 U1.23
  L3 w0.15: v1(32.96,26.95) 33.28,26.63 33.56,26.63 33.66,26.53 33.88,26.31 34.61,25.57 34.61,25.57 38.22,21.97 38.3,21.89 38.3,19.98 v1(36.38,18.06)
  BOTTOM w0.15: P2.6 37.64,17.5 36.94,17.5 v1(36.38,18.06)
PB0: length 19.6
  TOP w0.15: U1.5 19.89,19.87 19.89,19.87 v1(19.89,19.33)
  L3 w0.15: v1(19.89,19.33) 19.57,19.65 v1(13.08,19.65)
  BOTTOM w0.15: v1(13.08,19.65) 13.08,18.98 12.23,18.13 5.9,18.13 5.3,18.73 P1.3
PB1: length 19.8
  TOP w0.15: v1(8.48,22.09) 9.68,22.09 10.09,22.5 10.11,22.5 13.39,22.5 13.4,22.5 13.48,22.5 13.48,22.51 13.55,22.51 14.96,23.92 16.55,23.92 16.56,23.92 U1.54
  L3 w0.15: v1(8.48,22.09) 7.84,22.09 7.37,22.56 5.05,22.56 3.33,20.84 v1(3.33,18.08)
  BOTTOM w0.15: P1.5 4.42,17.64 3.77,17.64 v1(3.33,18.08)
PB2: length 24.8
  TOP w0.15: U1.53 16.27,24.42 14.97,24.42 13.35,22.8 13.27,22.8 13.27,22.8 9.83,22.8 9.65,22.62 v1(9.2,22.62)
  L3 w0.15: v1(9.2,22.62) 7.91,22.62 7.67,22.86 7.5,22.86 4.74,22.86 2.85,20.97 2.85,14 v1(3.2,13.65)
  BOTTOM w0.15: v1(3.2,13.65) P1.11
PB3: length 26.7
  TOP w0.15: v1(8.28,23.18) 13.3,23.18 14.84,24.72 16.14,24.72 16.17,24.72 16.37,24.92 U1.52
  L3 w0.15: v1(8.28,23.18) 4.5,23.18 2.55,21.23 2.55,13.02 v1(3.19,12.38)
  BOTTOM w0.15: v1(3.19,12.38) P1.13
PB4: length 29
  TOP w0.15: U1.51 16.42,25.42 16.02,25.02 14.72,25.02 13.18,23.48 8.89,23.48 v1(8.48,23.89)
  L3 w0.15: v1(8.48,23.89) 8.08,23.89 7.71,23.52 4.41,23.52 2.25,21.36 2.25,12.05 v1(3.2,11.1)
  BOTTOM w0.15: P1.15 3.37,11.11 3.36,11.1 v1(3.2,11.1)
PB5: length 31.3
  TOP w0.15: v1(9.21,24.22) 9.65,23.78 12.97,23.78 14.51,25.32 15.89,25.32 16.49,25.92 U1.50
  L3 w0.15: v1(3.2,9.84) 1.95,11.09 1.95,11.92 1.95,11.92 1.95,21.48 4.29,23.82 7.59,23.82 8.31,24.54 8.89,24.54 v1(9.21,24.22)
  BOTTOM w0.15: v1(3.2,9.84) P1.17
PB6/JTAG_TDI: length 43.3
  TOP w0.15: v1(12.55,24.28) 13.04,24.28 13.07,24.31 13.07,24.31 14.38,25.62 15.76,25.62 16.56,26.42 U1.49
  L3 w0.15: v1(33.68,9.82) 33.68,13 33.2,13.47 33.2,14.05 34.15,14.99 34.15,16.38 33.66,16.88 33.02,16.88 32.87,17.03 30.62,17.03 30.59,17 30.54,17 30.07,16.53 29.27,16.53 28.31,17.49 13.55,17.49 11.96,19.08 11.96,23.33 12.56,23.92 12.56,24.27 v1(12.55,24.28)
  BOTTOM w0.15: P2.17 33.89,9.84 33.87,9.82 v1(33.68,9.82)
PB7/JTAG_TDO: length 45.5
  TOP w0.15: U1.48 16.52,26.92 15.52,25.92 14.19,25.92 13.51,25.24 v1(12.36,25.24)
  L3 w0.15: v1(12.36,25.24) 12,24.88 12,23.79 11.66,23.45 11.66,18.96 13.43,17.19 28.19,17.19 29.16,16.22 30.19,16.22 30.67,16.7 32.77,16.7 32.9,16.58 33.38,16.58 33.83,16.13 33.83,15.1 32.9,14.17 32.9,13.35 33.17,13.08 33.17,9.06 v1(33.68,8.55)
  BOTTOM w0.15: v1(33.68,8.55) 33.95,8.55 33.97,8.57 P2.19
PC0: length 40.1
  TOP w0.15: R32.2 11.93,10.09 11.95,10.11 11.95,10.14 12.17,10.36 v1(12.17,10.9) ; v1(29.09,17.46) 28.25,17.46 v1(27.19,16.4) ; v1(25.5,19.43) 25.5,20.18 24.4,21.28 24.4,21.36 24.4,21.4 24.4,21.55 24.39,21.55 24.39,21.57 24.39,21.58 U1.14
  L3 w0.15: v1(29.09,17.46) 29.56,16.98 30.1,16.98 30.48,17.37 32.95,17.37 33.15,17.17 33.78,17.17 34.53,16.42 34.53,14.52 v1(33.68,13.67) ; v1(27.19,16.4) 27.19,15.7 27.19,15.7 27.19,15.17 25.87,13.85 24.22,13.85 22.85,12.48 14.31,12.48 12.73,10.9 v1(12.17,10.9)
  BOTTOM w0.15: P2.11 35.03,13.7 33.85,13.7 33.82,13.67 v1(33.68,13.67) ; v1(29.09,17.46) 27.12,19.43 v1(25.5,19.43)
PC1: length 22.2
  TOP w0.15: v1(25.52,18.72) 25.03,19.22 25.03,20.11 24.1,21.04 24.1,21.34 24.1,21.38 24.1,21.42 24.09,21.42 24.09,21.44 23.89,21.65 U1.13
  L3 w0.15: v1(29.9,17.46) 30.11,17.67 33.08,17.67 33.27,17.47 33.91,17.47 35,16.38 35,12.6 35.85,11.75 v1(36.36,11.75)
  BOTTOM w0.15: v1(36.36,11.75) 35.73,12.38 P2.13 35.06,12.4 ; v1(29.9,17.46) 29.42,16.98 28.82,16.98 28.56,17.24 27.07,18.72 v1(25.52,18.72)
PC2: length 55.7
  TOP w0.15: v1(24.54,19.48) 23.8,20.22 23.8,21.31 23.39,21.73 U1.12 ; R121.1 10.28,19.98 11.11,19.15 v1(13.61,19.15) ; v1(38.06,27.98) 37.74,27.66 37.73,27.66 34.67,24.6 34.67,24.59 v1(34.08,24) ; R3061.1 v1(26.4,37.2)
  L3 w0.15: v1(38.06,27.98) 38.06,28.67 38.01,28.71 38.01,29.11 38.06,29.15 38.06,31.79 32.65,37.2 v1(26.4,37.2) ; v1(34.08,24) 32.89,22.81 32.89,20.8 31.66,19.56 26.7,19.56 26.31,19.96 26.03,20.24 24.85,20.24 24.54,19.93 v1(24.54,19.48) 23.81,18.75 23.05,18.75 23.03,18.77 14.81,18.77 14.53,19.05 13.71,19.05 v1(13.61,19.15)
PC3: length 56.2
  TOP w0.15: v1(37.11,26.09) 36.79,25.77 36.79,25.76 v1(34.48,23.45) ; R3051.1 v1(26.4,36.3) ; v1(14.05,18.57) 13.52,18.57 13.35,18.74 R111.1 ; v1(24.51,18.65) 23.5,19.66 23.5,21.19 22.89,21.8 U1.11
  L3 w0.15: v1(26.4,36.3) 26.9,36.8 32.56,36.8 37.56,31.8 37.56,31.09 37.56,31.09 37.56,30.69 37.56,30.69 37.56,26.54 v1(37.11,26.09) ; v1(24.51,18.65) 24.51,18.62 24.46,18.57 ; v1(24.51,18.65) 25.03,19.17 25.03,19.63 25.3,19.91 25.88,19.91 26.53,19.27 31.78,19.27 33.19,20.67 33.19,21.22 34.48,22.51 v1(34.48,23.45) ; v1(24.51,18.65) 24.3,18.65 24.04,18.39 14.76,18.39 14.58,18.57 v1(14.05,18.57)
PC4: length 21.9
  TOP w0.15: v1(21.95,16.72) 21.95,17.21 21.69,17.47 21.69,21.2 21.89,21.4 21.89,22.22 U1.9
  L3 w0.15: v1(8.61,17.46) 10.59,15.48 18.25,15.48 19.18,16.41 19.18,16.41 19.42,16.65 19.62,16.85 21.82,16.85 v1(21.95,16.72)
  BOTTOM w0.15: v1(8.61,17.46) P1.6
PC5: length 21
  TOP w0.15: U1.8 21.39,21.59 21.39,21.59 v1(21.39,16.31)
  L3 w0.15: v1(21.39,16.31) 19.5,16.31 19.3,16.11 18.37,15.18 10.17,15.18 9.12,16.23 v1(8.67,16.23)
  BOTTOM w0.15: P1.8 7.24,16.23 v1(8.67,16.23)
PC6: length 21.5
  TOP w0.15: U1.7 20.89,21.59 21.07,21.41 21.07,16.66 20.63,16.22 v1(20.63,14.96)
  L3 w0.15: v1(20.63,14.96) 19.43,14.96 18.75,14.28 9.24,14.28 v1(8.61,14.91)
  BOTTOM w0.15: v1(8.61,14.91) 8.6,14.92 P1.10
PC7: length 21.2
  TOP w0.15: v1(19.66,14.4) 19.66,15.77 20.77,16.88 20.77,21.21 20.39,21.59 U1.6
  L3 w0.15: v1(8.6,13.67) 9.06,13.67 9.37,13.98 19.24,13.98 v1(19.66,14.4)
  BOTTOM w0.15: P1.12 7.23,13.68 8.39,13.68 8.4,13.67 v1(8.6,13.67)
PD0: length 26.1
  TOP w0.15: v1(32.48,27.65) 28.32,27.65 28.05,27.92 U1.25
  L3 w0.15: v1(36.38,14.28) 35.83,14.83 35.83,18.46 37.92,20.55 37.92,21.84 34.49,25.27 34.49,25.27 33.67,26.09 33.54,26.23 33.53,26.23 33.01,26.23 32.76,26.47 32.48,26.75 32.48,27.19 32.48,27.2 v1(32.48,27.65)
  BOTTOM w0.15: v1(36.38,14.28) 37.01,13.65 P2.12
PD1: length 28.1
  TOP w0.15: v1(32.53,28.42) 32.08,28.42 32.08,28.42 U1.26
  L3 w0.15: v1(36.38,13.04) 36.91,13.57 36.91,14.86 38.44,16.39 38.44,16.39 38.68,16.63 38.68,21.93 38.52,22.09 38.52,22.09 34.74,25.88 34.1,26.52 33.79,26.83 33.78,26.83 32.98,27.63 32.98,27.97 v1(32.53,28.42)
  BOTTOM w0.15: P2.14 36.64,12.38 36.38,12.64 v1(36.38,13.04)
PD2: length 31.6
  TOP w0.15: v1(38.49,28.91) R271.2 34.78,28.92 v1(34.06,28.92) 33.61,28.92 U1.27 ; R3071.1 v1(26.4,38.1)
  L3 w0.15: v1(38.49,28.91) 38.49,31.81 32.75,37.55 26.95,37.55 v1(26.4,38.1)
PD3: length 35.4
  TOP w0.15: v1(34.6,30.31) 28.27,30.31 27.75,30.83 26.03,30.83 25.33,30.12 U1.29
  L3 w0.15: v1(34.6,30.31) 35.36,29.55 35.36,26.96 39.89,22.43 39.89,17.06 40.2,16.75 40.2,15.67 39.97,15.44 39.97,10.7 v1(39.09,9.82)
  BOTTOM w0.15: P2.18 39.02,9.84 39.04,9.82 v1(39.09,9.82)
PD4: length 28.7
  TOP w0.15: U1.30 23.89,30.47 24.33,30.91 25.66,30.91 25.88,31.12 25.88,31.12 25.9,31.14 v1(33.01,31.14)
  L3 w0.15: v1(39.09,16.11) 39.09,16.59 38.99,16.69 38.99,22.05 38.98,22.06 38.98,22.06 38.82,22.22 38.82,22.22 36.5,24.54 36.5,24.54 34.86,26.18 34.22,26.82 33.91,27.13 33.91,27.13 33.28,27.76 33.28,28.11 33.01,28.38 v1(33.01,31.14)
  BOTTOM w0.15: v1(39.09,16.11) 38.93,16.11 38.85,16.19 P2.8
PD5: length 31.8
  TOP w0.15: v1(33.58,31.61) 33.13,31.61 33.12,31.61 25.94,31.61 25.75,31.42 25.75,31.42 25.54,31.21 24.13,31.21 23.39,30.47 U1.31
  L3 w0.15: v1(33.58,31.61) 33.58,27.89 34.35,27.12 34.99,26.48 34.99,26.48 36.8,24.67 39.29,22.18 39.29,16.81 39.56,16.54 39.56,15.88 39.14,15.46 v1(39.14,14.94)
  BOTTOM w0.15: P2.10 37.71,14.95 38.89,14.95 38.9,14.94 v1(39.14,14.94)
PD6: length 10.7
  TOP w0.15: R442.1 11.36,25.26 v1(11.36,24.3)
  L3 w0.15: P6.1 5.63,26.78 8.88,26.78 v1(11.36,24.3)
PD7: length 7.5
  TOP w0.15: R452.1 10.45,25.3 10.41,25.26 10.41,25.17 9.28,26.3 v1(8.36,26.3)
  L3 w0.15: P6.2 v1(8.36,26.3)
USB_N: length 18.9
  TOP w0.15: U1.3 18.89,20.51 11.96,13.58 11.96,12.11 v1(12.28,11.79) ; C21.1 9.35,10.2 v1(9.97,10.82) 9.97,10.26 10.22,10.01 R21.1
  L3 w0.15: v1(12.28,11.79) 11.31,10.82 v1(9.97,10.82)
USB_P: length 15.6
  TOP w0.15: R31.1 11.07,10.46 C31.1 11.08,10.47 11.62,11.02 11.62,13.67 18.39,20.43 18.39,21.59 18.39,21.59 U1.2
N05346: length 2.3
  TOP w0.15: U1.42 16.94,30.12 16.5,30.56 16.48,30.54 R421.2
N19179: length 4.1
  TOP w0.15: R32.1 R31.2 11.07,8.71
  TOP w0.2: 11.07,8.71 11.07,7.94 11.69,7.32 J1.3
N23099: length 9.4
  TOP w0.15: v1(25.8,32.73) 26.19,32.73 26.53,32.4 27.75,32.4 28.4,33.05 X1.1 C341.1 ; v1(22.34,31.11) 22.28,31.05 22.28,30.82 21.89,30.43 21.89,30.12 U1.34
  L3 w0.15: v1(25.8,32.73) 25.48,32.41 25.47,32.41 24.17,31.11 v1(22.34,31.11)
N24069: length 1.7
  TOP w0.15: R1.2 12.54,7.42 ; 12.34,6.25 J1.4
  TOP w0.2: 12.34,6.25 12.34,7.22 12.54,7.42
N28244: length 3.3
  TOP w0.15: R21.2 10.22,8.71
  TOP w0.2: J1.2 11.04,6.77 10.21,7.6 10.21,8.15 10.22,8.16 10.22,8.71
N31525: length 9.2
  TOP w0.15: v1(25.69,33.35) 26.01,33.67 26.42,33.67 27.25,34.5 X1.3 27.25,35.55 C351.1 ; v1(21.73,30.95) 21.73,30.89 21.39,30.55 U1.35
  L3 w0.15: v1(25.69,33.35) 24,31.66 22.21,31.66 21.73,31.18 v1(21.73,30.95)
N50825: length 24.9
  TOP w0.15: U2.3 v1(23.97,1.42)
  TOP w0.4: v1(18.07,1.44) C3.1 21.19,1.44 U2.1 ; J1.1 10.39,6.34 9.64,7.09 v1(9.36,7.09)
  L3 w0.15: v1(23.97,1.42) 18.54,1.42 18.52,1.44 v1(18.07,1.44)
  L3 w0.4: v1(9.36,7.09) 9.36,5.28 10.13,4.51 16.8,4.51 18.07,3.24 v1(18.07,1.44)
N61958: length 21.8
  TOP w0.15: R271.1 v1(34.14,28.11)
  L3 w0.15: v1(39.12,11.12) 39.67,11.67 39.67,15.56 39.86,15.76 39.86,16.66 39.59,16.94 39.59,22.3 37.1,24.79 35.11,26.78 34.46,27.43 34.46,27.79 v1(34.14,28.11)
  BOTTOM w0.15: v1(39.12,11.12) 39.11,11.11 P2.16
N118182: length 13.1
  TOP w0.5: P5.1 28.14,4.66 28.42,4.94
  TOP w0.6: FL2.2 28.42,7.15 ; 28.42,7.15 27.52,7.15 25.49,9.18 25.49,11.67 25.45,11.71 FL1.2 ; 28.42,7.15 28.42,4.94
N130966: length 1.2
  TOP w0.15: R3081.1 23.03,38.07 U3.8
N292030: length 2.3
  TOP w0.15: R121.2 v1(8.62,19.98)
  BOTTOM w0.15: v1(8.62,19.98) 7.22,19.98 P1.2
N292096: length 2.3
  TOP w0.15: R111.2 v1(8.66,18.74)
  BOTTOM w0.15: P1.4 7.21,18.74 v1(8.66,18.74)
N302598: length 2.2
  TOP w0.5: A1.1 C3109.1 C3110.2
N313805: length 5.4
  TOP w0.15: L3231.1 20.44,32.7 20.39,32.75
  TOP w0.3: L3231.1 20.45,32.8 U3.3 ; 20.39,32.75 U1.37
N313817: length 5.3
  TOP w0.15: L3231.2 19.89,32.7
  TOP w0.3: U3.2 19.8,32.75 L3231.2 ; 19.89,32.7 U1.38
N314459: length 3.3
  TOP w0.15: U3.7 22.05,37.5 24.34,37.5 24.94,38.1 R3071.2
N314634: length 3.2
  TOP w0.15: R3061.2 22.95,37.2 22.52,36.78 U3.6
N315094: length 3.5
  TOP w0.15: U3.5 22.3,36.12 23.07,36.9 24.34,36.9 24.94,36.3 R3051.2
N333392: length 2.9
  TOP w0.3: U3.10 C3101.1
  TOP w0.5: C3101.1 L3102.1 L3101.2
N333448: length 1.6
  TOP w0.5: L3104.2 C3105.1 C3110.1
N333456: length 1.8
  TOP w0.5: L3104.1 C3103.1 L3102.2
N355972: length 14.3
  TOP w0.26: J3.1 15.4,43.75 17.6,45.95 C3111.1
N359155: length 3.3
  TOP w0.15: R441.2 11.3,29.02 11.6,29.32 11.6,29.58 11.62,29.6 X2.1
  TOP w0.3: C441.1 12.58,30.5 X2.1
N359159: length 3.3
  TOP w0.15: X2.2 10.12,29.42 10.42,29.12 R451.2
  TOP w0.3: X2.2 C451.1
N359209: length 9.2
  TOP w0.15: R452.2 10.45,26.1 10.41,26.06 10.41,27 10.42,27.01 10.42,27.53 ; 10.42,27.53 R451.1 ; 10.42,27.53 10.97,26.98 12.66,26.98 12.8,27.12 15.01,27.12 16.31,28.42 U1.45
N359245: length 10.5
  TOP w0.15: v1(12.35,26.08) 11.38,26.08 R442.2 ; v1(12.35,27.53) R441.1 11.3,27.53 11.83,28.07 12.68,28.07 13.33,27.42 14.83,27.42 16.33,28.92 U1.44
  L3 w0.15: v1(12.35,27.53) v1(12.35,26.08)
N359999: length 3.1
  TOP w0.15: 26.35,30.31 26.39,30.31 ; 26.35,30.31 R281.2 ; 26.35,30.31 26.35,29.57 26.2,29.42 U1.28 ; 26.39,30.31 26.49,30.31 ; 26.39,30.31 26.39,29.5 C281.1
N362623: length 23.1
  TOP w0.15: 16.89,22.38 16.79,22.38 16.25,21.85 C561.1
  TOP w0.2: C321.1 24.55,31.76 24.16,31.76 22.89,30.49 22.89,30.12 U1.32
  TOP w0.3: U1.56 16.89,22.62 16.89,22.38 v1(16.9,22.39) ; v1(25.87,32.11) 25.56,31.8 C321.1
  L3 w0.3: v1(25.87,32.11) 24.25,30.49 24.25,23.27 24.04,23.06 18.1,23.06 17.43,22.39 v1(16.9,22.39)

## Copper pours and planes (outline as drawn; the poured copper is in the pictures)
GND on TOP (solid shape): 19.8,48.2 16.05,48.2 16.05,49.2 19.8,49.2
GND on TOP: 0.5,0.5 0.5,49.2 19.8,49.2 19.8,41.5 16.05,41.5 16.05,40.4 19.8,40.4 19.8,38.3 21.1,38.3 21.1,49.2 41.1,49.2 41.1,0.5 16.55,0.5 16.55,2.25 6.85,2.25 6.85,0.5 ; 11 cut-outs
GND on BOTTOM: 0.5,0.5 0.5,49.2 41.1,49.2 41.1,0.5 16.55,0.5 16.55,2.25 6.85,2.25 6.85,0.5 ; 1 cut-out
GND on L2: 0.5,0.5 0.5,49.2 41.1,49.2 41.1,0.5 16.55,0.5 16.55,2.25 6.85,2.25 6.85,0.5 ; 1 cut-out
GND on L3: 0.5,0.5 0.5,49.2 41.1,49.2 41.1,0.5 16.55,0.5 16.55,2.25 6.85,2.25 6.85,0.5 ; 15 cut-outs
VDD_CC2538 on L3: 31.6,19.7 17.5,19.7 14.6,22.6 14.6,30.3 19.2,34.9 26.8,34.9 32.9,28.8 32.9,21 ; 1 cut-out
Net_24 on TOP (solid shape): 35.17,54.9 18.77,54.9 18.77,53.1 19.77,53.1 19.77,52.6 20.68,51.28 20.68,49.2 20.22,49.2 20.22,51.13 19.7,51.89 16.57,51.89 16.57,53.1 17.57,53.1 17.57,53.9 11.77,53.9 11.77,51.23 19.77,51.23 19.77,49.2 18.77,49.2 18.77,49.94 17.57,49.94 17.57,49.2 16.57,49.2 16.57,49.94 9.59,49.94 9.59,56.11 35.17,56.11
N362623 on L3: 18.05,23 18.05,29.35 22.9,29.35 24.2,30.65 24.3,30.65 24.3,23

Small or netless copper shapes (teardrops, artwork), in the pictures only: 1 on TOP

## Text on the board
Ref Des/Silkscreen Bottom: Max 3.6V
Ref Des/Silkscreen Top: PD7 | PD6 | CC2538-CC2592 | Model: CC2538-CC2592EM | Revision:          2.0 | FCC ID:  ZAT25382592EM | IC:    451H-25382592EM | USB power | VDD | EB power
XSECTION_CHART: L1: TOP CONDUCTOR - COPPER 0.035 MM | *  DIELECTRIC - FR-4 0.175 MM | L2: L2 PLANE - COPPER 0.018 MM | *  DIELECTRIC - FR-4 1.14 MM | L3: L3 PLANE - COPPER 0.018 MM | L4: BOTTOM CONDUCTOR - COPPER 0.035 MM | DESIGN CROSS SECTION CHART | ___________________________ | TOTAL THICKNESS 1.596 MM
DIMENSION: FIGURE | SIZE | 0.2 | 1.1 | 1.501 | DRILL CHART: TOP to BOTTOM | ALL UNITS ARE IN MILLIMETERS | PLATED | NON-PLATED | QTY | 581 | 2 | 4
